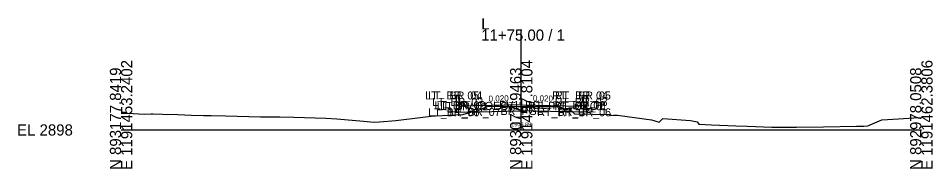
# Model space of a CAD drawing. Extents: x -26 to 203, y -10 to 7027.
# Drawn here: x -25.7 to 202.8, y 3490.3 to 3527.9 of the extents above; entities that cross this region are included whole.
import ezdxf

# ---------------------------------------------------------------- set-up
doc = ezdxf.new("R2010")
doc.units = 0
for name, color, linetype in [('Default', 7, 'Continuous'), ('Exist Cross Section Cell', 7, 'Continuous'), ('Prop CMT Pvmt Course 2 Wedge', 7, 'Continuous'), ('Prop CMT Pvmt Course 3 Wedge', 7, 'Continuous'), ('Prop CMT Pvmt Surface Shoulder', 7, 'Continuous'), ('Prop CMT Pvmt Wedge Surface 1', 7, 'Continuous'), ('Scratch_Level_6', 7, 'Continuous')]:
    doc.layers.add(name, color=color, linetype=linetype)

msp = doc.modelspace()

# ---------------------------------------------------------------- linework, layer by layer
at = {"layer": 'Exist Cross Section Cell'}
for p, q in [((100, 3500), (100, 3525.11)), ((0, 3500), (100, 3500)), ((100, 3500), (200, 3500))]:
    msp.add_line(p, q, dxfattribs=at)
at = {"layer": 'Prop CMT Pvmt Course 3 Wedge'}
for p, q in [((88.82, 3504.72), (91.62, 3505.92)), ((91.62, 3505.92), (95.77, 3505.9)), ((95.77, 3505.9), (99.55, 3505.88)), ((99.55, 3505.88), (100, 3505.89)), ((100, 3505.89), (100.51, 3505.9)), ((100.51, 3505.9), (104.77, 3505.9)), ((104.77, 3505.9), (108.28, 3505.9)), ((108.28, 3505.9), (109.46, 3505.78)), ((109.46, 3505.78), (111.38, 3505.09)), ((0, 3504.23), (1.65, 3504.18)), ((1.65, 3504.18), (5.77, 3503.97)), ((5.77, 3503.97), (7.49, 3504.02)), ((7.49, 3504.02), (7.97, 3504.01)), ((7.97, 3504.01), (10.33, 3503.98)), ((10.33, 3503.98), (14.16, 3503.83)), ((14.16, 3503.83), (17.48, 3503.73)), ((17.48, 3503.73), (20.6, 3503.62)), ((20.6, 3503.62), (22.49, 3503.58)), ((22.49, 3503.58), (26.1, 3503.52)), ((26.1, 3503.52), (34.83, 3503.24)), ((74.77, 3503.1), (78.14, 3503.51)), ((78.14, 3503.51), (78.54, 3503.53)), ((78.54, 3503.53), (85.4, 3503.87)), ((85.4, 3503.87), (87.4, 3504.43)), ((87.4, 3504.43), (88.82, 3504.72)), ((111.38, 3505.09), (111.83, 3505.46)), ((111.83, 3505.46), (113.35, 3504.01)), ((113.35, 3504.01), (122.28, 3503.84)), ((122.28, 3503.84), (122.3, 3503.61)), ((122.3, 3503.61), (123.07, 3503.73)), ((123.07, 3503.73), (124.03, 3503.68)), ((124.03, 3503.68), (132.57, 3502.49)), ((34.83, 3503.24), (35.27, 3503.24)), ((35.27, 3503.24), (39.65, 3503.25)), ((39.65, 3503.25), (43.15, 3503.18)), ((43.15, 3503.18), (51.2, 3502.98)), ((51.2, 3502.98), (53.88, 3502.79)), ((53.88, 3502.79), (60.58, 3502.18)), ((60.58, 3502.18), (63.28, 3501.95)), ((63.28, 3501.95), (64.54, 3502.03)), ((64.54, 3502.03), (68.69, 3502.36)), ((68.69, 3502.36), (74.77, 3503.1)), ((132.57, 3502.49), (134.47, 3501.95)), ((134.47, 3501.95), (135.39, 3502.83)), ((135.39, 3502.83), (142.33, 3502.34)), ((142.33, 3502.34), (144, 3502)), ((144, 3502), (144.43, 3501.41)), ((144.43, 3501.41), (147.56, 3501.31)), ((147.56, 3501.31), (153.67, 3501.04)), ((186.66, 3501), (187.19, 3501.24)), ((187.19, 3501.24), (190.13, 3502.54)), ((190.13, 3502.54), (194.27, 3502.81)), ((194.27, 3502.81), (198.13, 3503.02)), ((198.13, 3503.02), (200, 3503.13)), ((153.67, 3501.04), (156.49, 3500.96)), ((156.49, 3500.96), (162.6, 3500.73)), ((162.6, 3500.73), (164.93, 3500.69)), ((164.93, 3500.69), (166.39, 3500.7)), ((166.39, 3500.7), (168.78, 3500.69)), ((168.78, 3500.69), (175.54, 3500.79)), ((175.54, 3500.79), (183.81, 3500.95)), ((183.81, 3500.95), (185.63, 3500.98)), ((185.63, 3500.98), (186.66, 3501))]:
    msp.add_line(p, q, dxfattribs=at)
at = {"layer": 'Prop CMT Pvmt Wedge Surface 1'}
for points in [[(100, 3506.24), (89, 3506.01), (85.25, 3505.94), (85.24, 3506.19), (84.66, 3507.02), (84.49, 3508.61), (83.75, 3508.61), (83.75, 3504.41)], [(100, 3506.24), (111, 3506.01), (114.75, 3505.94), (114.76, 3506.19), (115.34, 3507.02), (115.51, 3508.61), (116.25, 3508.61), (116.25, 3504.41)], [(100, 3504.74), (100, 3506.24)], [(100, 3504.74), (100, 3506.24)], [(83.75, 3504.41), (89, 3504.51), (100, 3504.74)], [(116.25, 3504.41), (111, 3504.51), (100, 3504.74)]]:
    msp.add_lwpolyline(points, dxfattribs=at)

# ---------------------------------------------------------------- texts
at = {"layer": 'Default'}
msp.add_text('-', height=0.0001, dxfattribs=at).set_placement((0, 3500))
at = {"layer": 'Exist Cross Section Cell'}
for s, p in [('L', (90, 3525.11)), ('11+75.00 / 1', (90, 3522.31)), ('EL 2898', (-26, 3498.6))]:
    msp.add_text(s, height=2.8, dxfattribs=at).set_placement(p)
for s, p in [('E 1191453.2402', (2.8, 3490)), ('E 1191457.8104', (102.8, 3490)), ('E 1191462.3806', (202.8, 3490)), ('N 893177.8419', (0, 3490)), ('N 893077.9463', (100, 3490)), ('N 892978.0508', (200, 3490))]:
    msp.add_text(s, height=2.8, rotation=90, dxfattribs=at).set_placement(p)
at = {"layer": 'Prop CMT Pvmt Course 2 Wedge'}
for s, p in [('LT_ BR_05', (75.99, 3507.61)), ('LT_ BR_04', (76.73, 3507.61)), ('LT_BR_03', (77.71, 3506.02)), ('RT_ BR_04', (107.7, 3507.61)), ('RT_BR_03', (108.35, 3506.02)), ('RT_ BR_05', (108.44, 3507.61)), ('LT_BR_02', (78.3, 3505.19)), ('LT_BR_01', (78.87, 3504.94)), ('LT_PV1_OEOT', (79.74, 3505.01)), ('PV1_PGL', (94.47, 3505.24)), ('BR_PGL', (94.83, 3503.74)), ('RT_PV1_OEOT', (101.69, 3505.01)), ('RT_BR_02', (107.77, 3505.19)), ('RT_BR_01', (108.32, 3504.94)), ('LT_BR_06', (76.76, 3503.41)), ('LT_BR_07', (82.06, 3503.51)), ('RT_BR_07', (104.01, 3503.51)), ('RT_BR_06', (109.21, 3503.41))]:
    msp.add_text(s, height=2, dxfattribs=at).set_placement(p)
at = {"layer": 'Prop CMT Pvmt Surface Shoulder'}
for rotation, p in [(1.1458, (91.86, 3507.07)), (358.8542, (102.9, 3507.18))]:
    msp.add_text('0.020', height=1.5, rotation=rotation, dxfattribs=at).set_placement(p)
at = {"layer": 'Scratch_Level_6'}
msp.add_text('2903.89', height=1, dxfattribs=at).set_placement((97.51, 3500.89))

doc.saveas('drawing.dxf')
